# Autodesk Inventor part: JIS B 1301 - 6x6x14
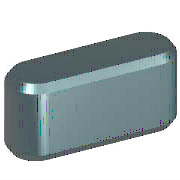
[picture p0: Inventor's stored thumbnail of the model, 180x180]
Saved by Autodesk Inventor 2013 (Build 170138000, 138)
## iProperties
Created: 2012-02
Part Number: JIS B 1301 - 6x6x14
Material: 강철, 연강
Description: 평행 키
Document SubType Name: Modeling
Standard: JIS B 1301
Designer: mdu-01
Standards Organization: JIS
Language: ko-KR
Size Designation: 6x6x14
Categories: <MemberInstance><Categories><Category DisplayName="샤프트 부품" InternalName="7f7aeb1f-a693-4053-b835-cee3144e0d98" Mnemonic="SHFT"><Category DisplayName="키" Interna
Density: 1 g/cm^3
IsCustomPart: 1
Author: mdu-01
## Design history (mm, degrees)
workplane "Work Plane1"
workplane "Work Plane2"
sketch "스케치1"
  geometry: L1 (3, 3)-(11, 3); L2 (11, -3)-(3, -3); L3 (0, 9.4)-(0, -7.4) reference; L4 (-5, 0)-(30, 0) reference; L5 (14, 0)-(14, 7); A1 r 3 centre (3, 0) between (3, 3) and (3, -3); A2 r 3 centre (11, 0) between (11, -3) and (11, 3)
  constraints: 6 end point, 5 point on circle, 4 tangent, 3 point on line, 2 centre point, 1 horizontal, 1 parallel, 1 perpendicular
  dimensions: "d0" = 3 radius of A1 (= 0.5 x PB); "d13" = 3 radius of A2 (= 0.5 x PB); "d14" = 14 distance between parallel lines of L5 L3 (= NLG)
extrude "본체1" new body sketch "스케치1" taper "d3" = 0 deg; stored distance "d4" = 10
workplane "Work Plane3"
body "Solid1"
chamfer "모따기1" distance "d8" = 0.4 (= PHH); stored, may be unused: second distance "d9" = 0.4 (= PHH), angle "d15" = 45 deg
other parameters: "d1" = -3.5 (= -PNT), "d2" = 2.5 (= PH - PNT), "NLG" = 14 [user parameter; used in 3 equation terms], "PB" = 6 [user parameter; used in 2 equation terms], "PNT" = 3.5 [user parameter; used in 2 equation terms], "PH" = 6 [user parameter; used in 1 equation term], "PHH" = 0.4 [user parameter; used in 2 equation terms], "d10" = 0, "d16" = 0, "d17" = 0, "d18" = 0, "WDMIN" = 17 [user parameter], "PLB2" = 14 (= NLG) [user parameter], "WDMAX" = 22 [user parameter], "PLB1" = 14 (= NLG) [user parameter], "RR" = 0.16 [user parameter], "PUEB" = 2.8 [user parameter]
